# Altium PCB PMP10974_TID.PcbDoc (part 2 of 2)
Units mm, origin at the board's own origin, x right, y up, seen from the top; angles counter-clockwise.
Board outline 80 x 60 mm, 2 copper layers (Top Layer, Bottom Layer), stack 1.575 mm thick; 90 components, 52 nets, 298 pads, 61 vias.
Unrouted connection lines stored in the file: 1.
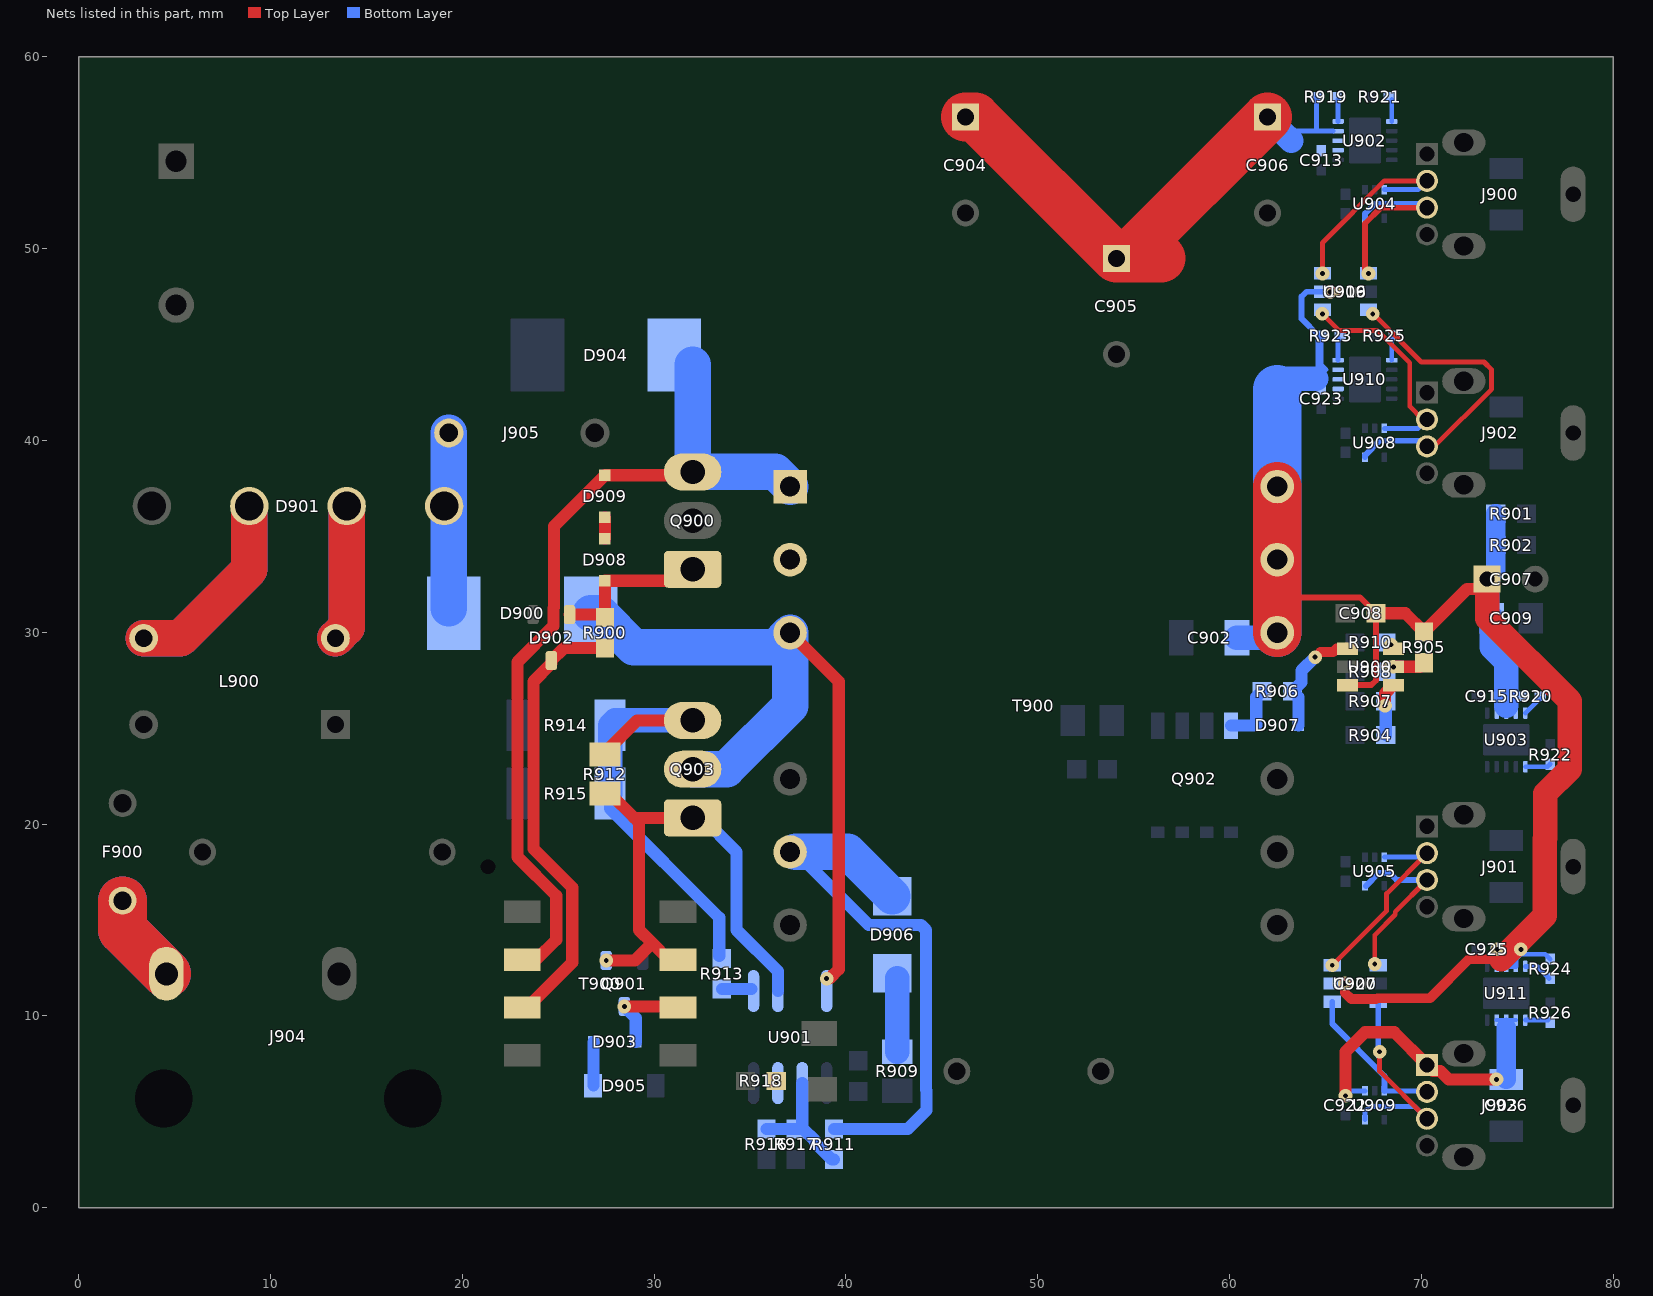
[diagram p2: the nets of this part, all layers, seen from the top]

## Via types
v1: diameter 0.711, hole 0.254, Top Layer to Bottom Layer, 44 vias
v2: diameter 0.5, hole 0.2, Top Layer to Bottom Layer, 16 vias
v3: diameter 1.524, hole 0.762, Top Layer to Bottom Layer, 1 vias

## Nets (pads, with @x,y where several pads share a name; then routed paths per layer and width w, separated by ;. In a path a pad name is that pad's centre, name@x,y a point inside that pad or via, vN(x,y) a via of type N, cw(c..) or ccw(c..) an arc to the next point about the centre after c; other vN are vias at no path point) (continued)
NetC922_1: C922.1 C926.1 J903.1 U909.1 U911.7 U911.8 U911.9 | length 17.3
  Top Layer w0.635: v1(66.04,5.834) 66.04,8.128 67.056,9.144 68.58,9.144 J903.1@70.29,7.434 70.598,7.127 70.981,7.127 71.424,6.684 v1(73.914,6.684)
  Bottom Layer w0.203: U911.9@73.922,9.776 U911.8@74.422,9.776 U911.7@74.922,9.776
  Bottom Layer w0.254: v1(66.04,5.834) 66.29,6.084 U909.1@67.064,6.084 ; 74.422,9.398 U911.8@74.422,9.776
  Bottom Layer w0.635: v1(73.914,6.684) C926.1@74.422,6.684
  Bottom Layer w1: C926.1@74.422,6.684 74.422,9.398
NetD900_1: D900.1 D901.1 J905.1 | length 9.1
  Bottom Layer w1.905: D900.1@19.29,31.243 J905.1@19.29,40.386
NetD900_2: D900.2 Q903.2 T900.3@37.084,29.972 U901.8 | length 41.1
  Top Layer w0.635: T900.3@37.084,29.972 39.624,27.432 39.624,12.43 39.134,11.94 v1(38.989,11.94)
  Bottom Layer w1.905: D900.2@26.682,30.988 27.162,30.988 28.94,29.21 36.322,29.21 T900.3@37.084,29.972 37.084,26.162 33.782,22.86 Q903.2@32.004,22.86
NetD901_2: D901.2 L900.2 | length 14.3
  Top Layer w1.905: L900.2@13.382,29.682 13.97,30.27 D901.2@13.97,36.576
  Bottom Layer w1.905: L900.2@13.382,29.682 13.97,30.27 D901.2@13.97,36.576
NetD901_3: D901.3 L900.3 | length 20.6
  Top Layer w1.905: L900.3@3.382,29.682 5.298,29.682 8.89,33.274 D901.3@8.89,36.576
  Bottom Layer w1.905: L900.3@3.382,29.682 5.298,29.682 8.89,33.274 D901.3@8.89,36.576
NetD902_1: D902.1 D908.1 Q900.1 R900.2 | length 7.6
  Top Layer w0.635: D902.1@25.588,30.918 R900.2@27.286,30.918 ; R900.2@27.432,30.772 D908.1@27.432,32.682 Q900.1@31.412,32.682
NetD902_3: D902.3 R900.1 T900.6@23.113,10.434 | length 23.6
  Top Layer w0.635: T900.6@23.113,10.434 23.388,10.434 25.727,12.773 25.727,16.691 23.706,18.712 23.706,27.432 24.638,28.364 D902.3@24.638,28.518 25.292,29.172 R900.1@27.432,29.172
NetD903_1: D903.1 D905.1 | length 2.3
  Bottom Layer w0.635: D905.1@26.84,6.38 D903.1@26.84,8.636
NetD903_2: D903.2 Q901.3 T900.3@31.243,10.434 | length 4.8
  Top Layer w0.635: v1(28.448,10.484) T900.3@31.193,10.484
  Bottom Layer w0.635: v1(28.448,10.484) 29.04,9.892 D903.2@29.04,8.636
NetD904_1: D904.1 D909.1 Q900.3 T900.1@37.084,37.592 T900.2@37.084,33.782 T900.7@23.113,12.934 | length 44.5
  Top Layer w0.635: T900.7@23.113,12.934 23.856,12.934 24.892,13.97 24.892,16.256 22.871,18.277 22.871,28.448 24.753,30.33 24.753,31.264 24.771,31.281 24.771,35.522 D909.1@27.432,38.184 Q900.3@31.834,38.184
  Bottom Layer w1.905: D904.1@32.004,43.955 Q900.3@32.004,38.354 36.322,38.354 T900.1@37.084,37.592
NetD906_1: D906.1 R909.2 | length 3.8
  Bottom Layer w1.27: R909.2@42.672,8.128 D906.1@42.672,11.97
NetD906_2: D906.2 R911.2 T900.5@37.084,18.542 | length 29.1
  Bottom Layer w0.635: T900.5@37.376,18.542 41.186,14.732 43.904,14.732 44.168,14.468 44.168,6.124 44.196,6.096 44.196,5.08 43.218,4.102 R911.2@39.37,4.102
  Bottom Layer w1.905: T900.5@37.376,18.542 40.1,18.542 D906.2@42.418,16.224
NetD907_1: D907.1 R906.2 U900.4 | length 5.2
  Top Layer w0.508: 64.731,28.973 65.407,28.973 65.578,29.144 U900.4@66.136,29.144
  Bottom Layer w0.635: R906.2@63.284,26.924 63.754,27.394 63.754,27.996 v1(64.46,28.702) ; D907.1@63.584,25.146 R906.2@63.584,26.624
NetD907_2: D907.2 Q902.4 R906.1 | length 3.2
  Bottom Layer w0.635: Q902.4@60.071,25.128 61.366,25.128 D907.2@61.384,25.146 61.384,26.624 R906.1@61.684,26.924
NetD908_2: D908.2 D909.2 | length 1.1
  Top Layer w0.635: D908.2@27.432,34.882 D909.2@27.432,35.984
NetF900_2: F900.2 J904.1 | length 9.5
  Top Layer w2.54: F900.2@2.286,16.002 2.286,14.476 J904.1@4.572,12.19
  Bottom Layer w2.54: F900.2@2.286,16.002 2.286,14.476 J904.1@4.572,12.19
NetJ900_2: J900.2 U904.3 U906.6 | length 10.8
  Top Layer w0.254: v1(64.84,48.702) 64.84,50.3 68.072,53.532 J900.2@70.29,53.532
  Bottom Layer w0.254: U904.3@68.064,53.074 69.832,53.074 J900.2@70.29,53.532
NetJ900_3: J900.3 U904.5 U906.1 | length 10
  Top Layer w0.305: v1(67.24,48.702) 67.056,48.886 67.056,51.308 67.88,52.132 J900.3@70.29,52.132
  Bottom Layer w0.305: U904.5@67.064,51.574 67.064,51.824 67.564,52.324 70.098,52.324 J900.3@70.29,52.132
NetJ901_2: J901.2 U905.3 U907.6 | length 9.9
  Top Layer w0.254: v1(65.348,12.634) 68.182,15.468 68.182,16.372 J901.2@70.29,18.48
  Bottom Layer w0.254: U905.3@68.064,18.276 J901.2@70.086,18.276
NetJ901_3: J901.3 U905.5 U907.1 | length 9.1
  Top Layer w0.254: v1(67.564,12.7) 67.564,14.208 68.636,15.28 68.636,15.426 J901.3@70.29,17.08
  Bottom Layer w0.305: U905.5@67.117,16.776 67.787,17.446 68.341,17.446 68.707,17.08 J901.3@70.29,17.08
NetJ902_2: J902.2 U906.4 U908.3 | length 11.3
  Top Layer w0.254: v1(64.835,46.598) 65.713,45.72 67.716,45.72 69.388,44.048 69.388,41.776 J902.2@70.078,41.086
  Bottom Layer w0.254: U908.3@68.064,40.628 69.832,40.628 J902.2@70.29,41.086
NetJ902_3: J902.3 U906.3 U908.5 | length 16.4
  Top Layer w0.254: v1(67.463,46.598) 67.481,46.598 69.99,44.088 73.26,44.088 73.66,43.688 73.66,43.503 73.662,43.501 73.662,42.669 J902.3@70.679,39.686
  Bottom Layer w0.305: U908.5@67.064,39.128 67.064,39.228 67.818,39.982 69.994,39.982 J902.3@70.29,39.686
NetJ903_2: J903.2 U907.4 U909.3 | length 7.9
  Bottom Layer w0.254: U909.3@68.066,6.084 J903.2@70.24,6.084
  Bottom Layer w0.305: U907.4@65.348,10.734 65.348,9.582 68.066,6.864 U909.3@68.066,6.084
NetJ903_3: J903.3 U907.3 U909.5 | length 11.4
  Top Layer w0.254: v1(67.818,8.128) 67.818,7.106 J903.3@70.29,4.634
  Bottom Layer w0.254: U909.5@67.064,4.584 67.064,5.028 67.31,5.274 69.65,5.274 J903.3@70.29,4.634
  Bottom Layer w0.305: v1@67.748,7.896 U907.3@67.748,10.734
NetQ901_1: Q901.1 Q903.1 R912.2 T900.2@31.243,12.934 U901.6 | length 27.7
  Top Layer w0.635: R912.2@27.432,21.59 27.686,21.59 28.956,20.32 ; v1(27.498,12.884) 28.993,12.884 29.899,13.789 ; T900.2@31.243,12.934 31.223,12.954 30.734,12.954 29.899,13.789 ; Q903.1@32.004,20.32 28.956,20.32 ; 28.956,20.32 29.21,20.066 29.21,14.478 29.899,13.789
  Bottom Layer w0.635: Q903.1@32.004,20.32 32.512,20.32 34.29,18.542 34.29,14.478 36.449,12.319 U901.6@36.449,11.29
NetQ903_3: Q903.3 R912.1 R913.2 R914.2 R915.2 | length 24.2
  Top Layer w0.635: R912.1@27.432,23.622 27.432,23.723 29.109,25.4 Q903.3@32.004,25.4
  Bottom Layer w0.635: R915.2@27.7,21.59 27.7,20.814 33.396,15.118 R913.2@33.396,13.123
  Bottom Layer w1.27: R915.2@27.7,21.59 R914.2@27.7,25.146 27.954,25.4 Q903.3@32.004,25.4
NetR904_1: R904.1 R907.2 U900.1 | length 2.7
  Top Layer w0.635: v1(68.098,26.162) 68.098,26.806 U900.1@68.536,27.244
  Bottom Layer w0.635: R904.1@68.136,24.638 R907.2@68.136,26.124
NetR905_1: R905.1 R908.2 U900.2 | length 1.7
  Top Layer w0.635: v1(68.536,28.194) 69.914,28.194 R905.1@70.13,28.41
NetR910_1: R910.1 U900.3
  other v1: 68.417,29.348
NetR911_1: R911.1 R916.2 R917.2 U901.2 | length 6.6
  Bottom Layer w0.635: R916.2@35.851,4.102 R917.2@37.375,4.102 37.77,4.102 38.378,3.494 38.378,3.388 39.263,2.502 R911.1@39.37,2.502 ; R917.2@37.719,4.153 U901.2@37.719,6.49
NetR913_1: R913.1 U901.5 | length 1.5
  Bottom Layer w0.635: R913.1@33.528,11.392 U901.5@35.077,11.392
NetR918_2: R918.2 U901.3
  other v1: 36.434,6.604
NetR919_1: R919.1 U902.5 | length 1.2
  Bottom Layer w0.254: U902.5@65.656,56.626 R919.1@65.656,57.78
NetR920_1: R920.1 U903.5 | length 1.1
  Bottom Layer w0.254: U903.5@75.422,25.784 R920.1@76.192,26.554
NetR921_2: R921.2 U902.6 | length 1.1
  Bottom Layer w0.254: U902.6@68.456,56.626 R921.2@68.456,57.774
NetR922_2: R922.2 U903.6 | length 1.3
  Bottom Layer w0.254: U903.6@75.422,22.984 76.57,22.984 R922.2@76.708,23.122
NetR923_1: R923.1 U910.5 | length 1.2
  Bottom Layer w0.254: U910.5@65.656,44.18 R923.1@65.656,45.344
NetR924_1: R924.1 U911.5 | length 1.5
  Bottom Layer w0.254: U911.5@75.422,12.576 76.024,12.576 R924.1@76.654,11.946
NetR925_2: R925.2 U910.6 | length 1.2
  Bottom Layer w0.254: U910.6@68.456,44.18 R925.2@68.456,45.35
NetR926_2: R926.2 U911.6 | length 1.2
  Bottom Layer w0.254: U911.6@75.422,9.776 R926.2@76.592,9.776
VOUT: C902.1 C904.1 C905.1 C906.1 C907.1 C908.1 C909.1 C913.1 C915.1 C919.1 C920.1 C923.1 C925.1 R901.2 R902.2 R905.2 R919.2 R920.2 R923.2 R924.2 T900.10 T900.11 T900.12 U900.6 U902.2 U902.3 U902.4 U903.2 U903.3 U903.4 U906.5 U907.5 U910.2 U910.3 U910.4 U911.2 U911.3 U911.4 | length 126.2
  Top Layer w0.305: 62.549,31.815 66.801,31.815 C908.1@67.628,30.988 67.628,27.486 67.386,27.244 U900.6@66.136,27.244
  Top Layer w0.508: v1(65.998,11.684) 65.998,11.218 66.342,10.874 67.645,10.874 67.693,10.922 70.46,10.922 72.492,12.954 74.168,12.954
  Top Layer w0.635: C908.1@67.628,30.988 69.152,30.988 R905.2@70.13,30.01 72.378,32.258 72.918,32.258 C907.1@73.426,32.766
  Top Layer w1.27: C907.1@73.426,32.766 73.426,30.714 77.724,26.416 77.724,22.86 76.454,21.59 76.454,19.253 76.425,19.224 76.425,15.211 74.168,12.954
  Top Layer w2.54: C904.1@46.228,56.856 46.736,56.856 C905.1@54.102,49.49 C905.1@54.61,49.49 ; 56.428,49.49 C905.1@54.61,49.49 ; C906.1@61.976,56.856 C905.1@54.61,49.49 ; T900.10@62.484,29.972 T900.11@62.484,33.782 T900.12@62.484,37.592
  Bottom Layer w0.254: 62.706,56.126 U902.4@65.396,56.126 ; 64.524,56.134 R919.2@64.524,57.912 ; R923.2@64.778,45.466 64.778,43.934 65.032,43.68 ; U911.2@73.922,12.576 U911.3@74.422,12.576 U911.4@74.922,12.576 74.922,12.946 75.184,13.208 76.446,13.208 R924.2@76.708,12.946
  Bottom Layer w0.305: 64.516,43.218 64.632,43.334 64.632,45.466 63.754,46.344 63.754,47.498 64.008,47.752 U906.5@64.84,47.752
  Bottom Layer w1: C907.1@73.426,32.766 73.876,33.216 R902.2@73.876,34.544 R901.2@73.876,36.176
  Bottom Layer w1.27: C902.1@60.378,29.718 T900.10@62.23,29.718 ; C906.1@61.976,56.856 62.706,56.126 63.206,55.626 ; 62.7,43.218 64.516,43.218 ; C907.1@73.426,32.766 73.426,30.968 C909.1@73.66,30.734 73.66,29.21 74.422,28.448 74.422,26.162
  Bottom Layer w2.54: T900.10@62.484,29.972 T900.11@62.484,33.782 T900.12@62.484,37.592 62.484,42.672
  other v1: 73.956,13.462 75.184,13.462 65.24,47.737
pads on no net: D902.2 J904.MH1 J904.MH2 T900.1@31.243,15.434 T900.4 T900.5@23.113,7.934 T900.8@23.113,15.434 U902.10 U903.10 U904.2 U905.2 U908.2 U909.2 U910.10 U911.10

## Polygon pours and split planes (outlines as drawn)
VOUT on Bottom Layer "Vout" (solid, remove dead copper, pour order 40): 65.786,55.118 65.786,56.642 65.786,57.658 65.786,58.674 64.77,59.69 63.687,59.69 44.45,59.69 44.196,59.436 44.196,58.166 44.196,57.488 53.148,48.536 53.17,48.514 54.864,48.514 54.864,49.53 60.452,55.118
GND2 on Bottom Layer "GND2" (solid, remove dead copper, pour order 42): 52.578,0.762 53.086,0.254 54.102,0.254 76.2,0.254 79.248,0.254 79.756,0.762 79.756,1.27 79.756,9.144 79.756,32.766 79.756,59.182 79.248,59.69 78.232,59.69 66.548,59.69 44.45,59.69 44.196,59.436 44.196,58.42 44.196,52.578 44.196,51.054 44.196,50.8 46.482,48.514 48.768,46.228 48.768,38.354 48.768,35.306 48.768,23.622 51.054,21.336 52.578,19.812 52.578,18.796
NetC910_2 on Bottom Layer "C910_2" (solid, remove dead copper, pour order 25): 53.34,12.192 53.594,11.938 55.118,11.938 59.69,11.938 62.992,11.938 64.77,13.716 65.278,14.224 65.278,18.288 65.278,18.542 65.786,19.05 67.056,20.32 67.056,23.876 67.056,24.638 66.802,24.892 66.461,24.892 65.786,24.892 64.262,23.368 57.912,23.368 53.594,23.368 53.34,23.114
NetD904_1 on Bottom Layer "D904_1" (solid, remove dead copper, pour order 27): 30.48,45.974 30.48,44.881 30.505,44.856 30.48,44.831 30.48,44.704 30.48,40.64 30.48,37.846 30.734,37.592 31.242,37.592 35.052,37.592 36.068,36.576 36.576,36.576 38.1,36.576 38.354,36.83 38.354,39.624 38.354,45.72 38.1,45.974
NetQ903_3 on Bottom Layer "Q903_3" (solid, remove dead copper, pour order 28): 33.274,26.416 33.499,26.191 33.499,26.162 33.499,25.908 33.499,24.892 33.499,24.863 33.274,24.638 32.766,24.638 30.48,24.638 29.718,23.876 29.718,23.368 29.718,21.336 28.702,20.32 28.522,20.14 27.178,20.14 27.104,20.14 26.67,20.574 26.416,20.828 26.416,21.336 26.416,26.162 26.67,26.416
NetD900_2 on Bottom Layer "D900_2" (solid, remove dead copper, pour order 29): 25.4,32.512 28.207,32.512 28.702,32.512 29.21,32.004 29.972,31.242 30.988,31.242 37.592,31.242 38.1,30.734 38.1,30.48 38.1,27.432 38.1,25.4 37.338,24.638 36.576,23.876 36.322,23.876 36.068,23.622 34.544,22.098 33.02,22.098 33.02,23.368 34.544,24.892 34.544,26.162 34.544,26.924 34.036,27.432 33.499,27.432 30.988,27.432 30.48,27.94 29.21,27.94 25.908,27.94 25.4,28.448
NetC914_1 on Bottom Layer "C914" (solid, remove dead copper, pour order 32): 68.326,56.134 69.596,56.134 70.104,56.134 70.866,55.372 71.628,54.61 74.168,54.61 75.068,54.61 75.322,54.356 75.322,54.102 75.322,53.478 74.93,53.086 73.406,53.086 71.882,53.086 70.612,54.356 70.578,54.39 69.63,54.39 69.302,54.39 68.86,54.832 68.574,55.118 68.326,55.118
VOUT on Bottom Layer "Vout" (solid, remove dead copper, pour order 33): 62.484,48.006 59.69,45.212 59.69,35.814 59.69,29.21 60.198,28.702 61.328,28.702 62.992,28.702 63.754,29.464 63.754,30.48 63.754,39.116 63.754,41.656 64.008,41.91 64.262,42.164 64.516,42.164 64.719,42.164 65.069,42.515 65.227,42.672 65.506,42.672 65.786,42.672 65.786,43.688 65.278,44.196 65.278,45.166 65.278,45.466 64.516,46.228 64.516,46.99 64.77,47.244 65.024,47.244 65.278,47.244 65.532,47.498 65.54,47.506 65.54,47.752 65.532,47.752 65.278,48.006
NetC921_1 on Bottom Layer "C921_1" (solid, remove dead copper, pour order 34): 68.326,43.688 69.85,43.688 70.104,43.688 71.374,42.418 74.168,42.418 75.184,42.418 75.438,42.164 75.438,41.91 75.438,41.148 75.184,40.894 74.93,40.894 70.612,40.894 69.088,42.418 68.326,42.418
NetC917_1 on Bottom Layer "C917_1" (solid, remove dead copper, pour order 37): 73.914,23.114 74.93,23.114 74.93,22.834 74.956,22.834 75.184,22.606 75.438,22.352 75.438,20.066 75.438,18.816 75.184,18.562 75.184,18.542 74.168,18.542 71.374,18.542 70.358,18.542 69.596,19.304 69.596,20.32 69.85,20.574 70.866,20.574 71.628,19.812 73.152,19.812 73.406,20.066 73.406,20.828 73.406,22.352 73.66,22.606 73.888,22.834 73.914,22.834
VOUT on Bottom Layer "Vout" (solid, remove dead copper, pour order 38): 73.914,12.446 73.914,12.7 73.66,12.954 73.66,13.162 73.66,13.416 73.706,13.462 73.66,13.508 73.66,13.97 73.914,14.224 74.168,14.478 75.184,14.478 76.454,14.478 76.514,14.478 76.962,14.03 76.962,13.716 76.962,12.954 76.454,12.446 75.184,12.446
VOUT on Bottom Layer "Vout" (solid, remove dead copper, pour order 39): 73.914,25.654 74.93,25.654 74.93,25.934 74.956,25.934 75.184,26.162 75.438,26.416 75.438,28.448 74.422,29.464 74.422,31.242 74.422,32.258 74.422,34.069 74.422,36.322 74.168,36.576 73.914,36.576 72.898,36.576 72.644,36.322 72.644,36.068 72.644,35.306 72.644,34.798 72.644,33.274 72.644,31.496 72.644,28.956 72.644,28.194 73.66,27.178 73.66,27.02 73.66,26.162 73.914,25.908 73.914,25.654
NetC922_1 on Bottom Layer "C922_1" (solid, remove dead copper, pour order 36): 69.596,7.874 69.85,8.128 70.612,8.128 70.866,8.128 71.628,7.366 73.152,7.366 73.406,7.62 73.406,9.084 73.406,9.144 73.914,9.652 73.914,9.906 74.93,9.906 74.93,9.652 75.438,9.144 75.438,8.636 75.438,7.62 75.438,6.35 74.676,6.35 73.406,6.35 70.104,6.35 69.596,6.858
GND on Bottom Layer "GND" (solid, remove dead copper, pour order 46): 46.482,0.762 45.974,0.254 45.466,0.254 38.354,0.254 26.162,0.254 25.654,0.762 25.654,2.286 25.654,17.526 22.098,21.082 22.098,21.844 21.59,22.352 21.082,22.86 21.082,41.402 19.812,42.672 19.558,42.672 9.906,42.672 5.334,38.1 5.334,36.322 5.334,35.558 4.572,34.796 1.778,34.796 1.044,34.796 0.28,35.56 0.254,35.586 0.254,36.068 0.254,39.116 0.254,44.704 0.254,59.182 0.762,59.69 2.032,59.69 24.384,59.69 38.354,45.72 42.418,41.656 42.418,34.798 42.418,29.718 42.418,19.304 42.418,19.05 46.482,14.986
GND2 on Top Layer "GND2" (solid, remove dead copper, pour order 41): 52.578,0.762 53.086,0.254 54.102,0.254 76.2,0.254 79.248,0.254 79.756,0.762 79.756,1.27 79.756,9.144 79.756,32.766 79.756,59.182 79.248,59.69 78.232,59.69 66.548,59.69 44.45,59.69 44.196,59.436 44.196,58.42 44.196,52.578 44.196,51.054 44.196,50.8 46.482,48.514 48.768,46.228 48.768,38.354 48.768,35.306 48.768,23.622 51.054,21.336 52.578,19.812 52.578,18.796
NetC910_2 on Top Layer "C910_2" (solid, remove dead copper, pour order 26): 55.626,23.368 55.118,23.368 54.864,23.114 54.864,22.606 54.864,18.796 54.864,16.256 54.864,12.192 55.118,11.938 55.88,11.938 62.992,11.938 65.278,14.224 65.278,15.537 65.278,23.114 65.024,23.368
VOUT on Top Layer "Vout" (solid, remove dead copper, pour order 30): 62.23,28.702 62.992,28.702 63.754,29.464 63.754,29.972 63.754,32.766 63.754,42.164 60.452,45.466 60.452,51.562 60.452,53.086 63.246,55.88 63.246,58.42 63.246,59.436 62.992,59.69 62.484,59.69 44.45,59.69 44.196,59.436 44.196,58.674 44.196,56.642 54.864,45.974 55.626,45.212 55.626,33.528 55.626,29.604 56.528,28.702
VOUT on Top Layer "Vout" (solid, remove dead copper, pour order 35): 63.5,36.068 66.04,36.068 68.834,36.068 71.628,36.068 74.168,33.528 74.168,33.02 74.168,31.496 78.486,27.178 78.486,26.67 78.486,21.082 77.216,19.812 77.216,17.272 77.216,14.478 75.184,12.446 73.66,12.446 73.406,12.7 73.406,12.954 73.406,13.462 73.406,13.716 74.168,14.478 75.438,15.748 75.438,20.828 75.438,22.098 75.692,22.352 76.2,22.86 76.2,24.522 76.2,25.146 71.882,29.464 71.628,29.464 69.85,29.464 68.834,30.48 67.818,30.48 67.31,30.988 67.12,31.178 67.12,31.496 67.056,31.496 66.802,31.75 63.5,31.75
GND on Top Layer "GND" (solid, remove dead copper, pour order 43): 46.482,0.762 45.974,0.254 45.466,0.254 38.354,0.254 26.162,0.254 25.654,0.762 25.654,2.286 25.654,17.526 22.098,21.082 22.098,21.844 21.59,22.352 21.082,22.86 21.082,41.402 19.812,42.672 19.558,42.672 9.906,42.672 5.334,38.1 5.334,36.322 5.334,35.558 4.572,34.796 1.778,34.796 1.044,34.796 0.28,35.56 0.254,35.586 0.254,36.068 0.254,39.116 0.254,44.704 0.254,59.182 0.762,59.69 2.032,59.69 24.384,59.69 38.354,45.72 42.418,41.656 42.418,34.798 42.418,29.718 42.418,19.304 42.418,19.05 46.482,14.986

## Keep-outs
Keep-Out Layer:
  text ".Layer_Name" at 14.656,-21.806 h1.52

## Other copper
Top Layer:
  text ".Layer_Name" at 14.656,-21.806 h1.52
Bottom Layer:
  text ".Layer_Name" at 14.656,-21.806 h1.52

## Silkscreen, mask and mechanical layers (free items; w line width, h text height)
Top Overlay:
  lines w0.178: 7.62,41.91 7.62,59.91 40.62,59.91 40.62,41.91 7.62,41.91
  lines w0.254: 25.146,33.274 25.908,33.274 26.162,33.528
  text ".PRJ_Number" at 46.482,0.762 h1.52
  text ".PCB_Rev" at 61.722,0.762 h1.52
  text ".Layer_Name" at 14.656,-21.806 h1.52
Bottom Overlay:
  lines w0.254: 32.258,0.762 36.83,0.762 37.338,1.27 ; 39.37,1.27 39.878,0.762 40.894,0.762 ; 63.5,23.876 64.516,22.86 65.786,22.86 ; 63.754,43.942 64.516,43.942 64.77,43.688 ; 67.818,51.054 69.342,49.53 69.342,49.276 ; 73.406,27.178 74.168,27.94 ; 76.962,26.67 77.724,26.67 77.978,26.416
  text ".Layer_Name" at 14.656,-21.806 h1.52
Top Paste:
  text ".Layer_Name" at 14.656,-21.806 h1.52
Bottom Paste:
  text ".Layer_Name" at 14.656,-21.806 h1.52
Top Solder:
  text ".Layer_Name" at 14.656,-21.806 h1.52
  text ".Layer_Name" at 14.656,-21.806 h1.52
Bottom Solder:
  text ".Layer_Name" at 14.656,-21.806 h1.52
Drill Guide:
  text ".Layer_Name" at 14.656,-21.806 h1.52
M1 Board Outline:
  the board outline again, w0.178
  text ".Layer_Name" at 14.656,-21.806 h1.52
M2 Board Dimensions:
  rectangle: 0,-6.985 3.175,-3.81
  rectangle: 3.175,-10.16 12.7,-6.985
  lines w0.178: 0,-6.985 25.4,-6.985 ; 3.175,-10.16 3.175,-3.81 ; 6.35,-10.16 6.35,-3.81 ; 12.7,-10.16 12.7,-3.81 ; 19.05,-10.16 19.05,-3.81 ; 0,-10.16 25.4,-10.16 25.4,-3.81 0,-3.81 0,-10.16
  text ".Layer_Name" at 14.656,-21.806 h1.52
M3 3D STEP Top:
  text ".Layer_Name" at 14.656,-21.806 h1.52
M4 3D STEP Bottom:
  text ".Layer_Name" at 14.656,-21.806 h1.52
M5 Assembly Top:
  lines w0.254: -7.417,-23.626 160.223,-23.626 ; -7.417,-18.462 160.274,-18.462 ; -7.417,-13.297 -7.417,-28.791 94.31,-28.791 160.274,-28.791 160.274,-13.297 -7.404,-13.297 -7.404,-28.791 32.614,-28.791 ; 55.194,-28.791 55.194,-13.297 ; 87.376,-18.462 87.376,-13.297 ; 108.712,-18.462 108.712,-13.297 ; 124.511,-28.956 124.511,-23.804
  text "COMPONENTS MARKED 'DNP' SHOULD NOT BE POPULATED." at 29.299,-8.09 h1.52
  text "ASSEMBLY VARIANT:" at 29.286,-11.024 h1.52
  text ".VariantName" at 55.601,-11.024 h1.52
  text "PCB VIEWED FROM TOP SIDE" at -5.804,-16.654 h1.52
  text "BOARD #:" at 57.099,-16.654 h1.52
  text ".PRJ_Number" at 70.955,-16.654 h1.52
  text "REV:" at 92.405,-16.654 h1.52
  text ".PCB_Rev" at 99.809,-16.654 h1.52
  text "SVN REV:" at 113.69,-16.654 h1.52
  text ".VersionControl_RevNumber" at 126.543,-16.654 h1.52
  text "PLOT NAME =" at -5.804,-27.034 h1.52
  text ".plot_File_Name" at 14.656,-27.034 h1.52
  text "GENERATED    :" at 57.15,-27.034 h1.52
  text ".Print_Date" at 79.235,-27.034 h1.52
  text ".Print_Time" at 97.752,-27.034 h1.52
  text "TEXAS INSTRUMENTS" at 129.87,-27.034 h1.52
M6 Assembly Bottom:
  lines w0.254: -7.429,-18.474 160.261,-18.474 ; -7.379,-23.639 160.261,-23.639 ; 28.334,-28.969 28.334,-23.817 ; 44.133,-18.474 44.133,-13.31 ; 65.468,-18.474 65.468,-13.31 ; 97.65,-28.804 97.65,-13.31 ; 120.231,-28.804 160.249,-28.804 160.249,-13.31 -7.429,-13.31 -7.429,-28.804 58.534,-28.804 160.261,-28.804 160.261,-13.31
  text "COMPONENTS MARKED 'DNP' SHOULD NOT BE POPULATED." at 154.991,-8.077 h1.52
  text ".VariantName" at 128.473,-11.024 h1.52
  text "ASSEMBLY VARIANT:" at 154.864,-11.024 h1.52
  text ".VersionControl_RevNumber" at 26.302,-16.667 h1.52
  text "SVN REV:" at 39.154,-16.667 h1.52
  text ".PCB_Rev" at 53.035,-16.667 h1.52
  text "REV:" at 60.439,-16.667 h1.52
  text ".PRJ_Number" at 81.89,-16.667 h1.52
  text "BOARD #:" at 95.745,-16.667 h1.52
  text "PCB VIEWED FROM BOTTOM SIDE" at 158.648,-16.667 h1.52
  text "TEXAS INSTRUMENTS" at 22.974,-27.047 h1.52
  text ".Print_Time" at 55.093,-27.047 h1.52
  text ".Print_Date" at 73.609,-27.047 h1.52
  text "GENERATED    :" at 95.694,-27.047 h1.52
  text ".plot_File_Name" at 138.189,-27.047 h1.52
  text "PLOT NAME =" at 158.648,-27.047 h1.52
M9 Title Sheet:
  drawing of 57 lines, arcs and shapes, not listed
  text "1" at 18.792,204.127 h1.78
  text "2" at 82.182,204.127 h1.78
  text "3" at 145.411,204.127 h1.78
  text "4" at 209.08,204.127 h1.78
  text "5" at 272.555,204.127 h1.78
  text "6" at 336.182,204.127 h1.78
  text "A" at -10.579,175.095 h1.78
  text "A" at 365.341,175.095 h1.78
  text "B" at -10.579,114.643 h1.78
  text "B" at 365.341,114.643 h1.78
  text "C" at -10.579,54.318 h1.78
  text "C" at 365.341,54.318 h1.78
  text "PROJECT TITLE:" at 288.125,7.048 h1.14
  text ".PRJ_Title" at 289.395,3.662 h1.78
  text "DESIGNED FOR:" at 288.125,-0.597 h1.14
  text ".PRJ_Customer" at 289.395,-4.153 h1.78
  text "D" at -10.579,-5.88 h1.78
  text "D" at 365.341,-5.88 h1.78
  text "FILE NAME:" at 288.125,-8.217 h1.14
  text ".PCB_File_Name_No_Path" at 289.395,-11.265 h1.78
  text "Texas Instruments (TI) and/or its licensors do not warrant the accuracy or completeness of this specification" at 161.9,-15.376 h1.14
  text "ENGINEER:" at 288.125,-15.583 h1.14
  text "LAYOUT BY:" at 326.352,-15.583 h1.14
  text "or any information contained therein. TI and/or its licensors do not warrant that this design will meet" at 160.757,-18.237 h1.14
  text ".PRJ_Engineer" at 289.395,-19.52 h1.78
  text ".PCB_Layout" at 327.635,-19.52 h1.78
  text "the specifications, will be suitable for your application or fit for any particular purpose, or will operate in" at 160.757,-21.099 h1.14
  text ".Layer_Name" at 14.656,-21.806 h1.52
  text "ALTIUM DESIGNER VERSION:" at 326.352,-23.457 h1.14
  text "an implementation. TI and/or its licensors do not warrant that the design is production worthy. You should" at 160.757,-23.961 h1.14
  text "completely validate and test your design implementation to confirm the system functionality for your application." at 161.9,-26.822 h1.14
  text ".print_Scale" at 289.395,-26.843 h1.78
  text ".Application_BuildNumber" at 327.635,-26.843 h1.78
  text "1" at 18.792,-32.093 h1.78
  text "2" at 82.182,-32.093 h1.78
  text "3" at 145.411,-32.093 h1.78
  text "4" at 209.08,-32.093 h1.78
  text "5" at 272.555,-32.093 h1.78
  text "6" at 336.182,-32.093 h1.78
M10 Fab Notes:
  drawing of 185 lines, arcs and shapes, not listed
  text "DESIGN INFORMATION" at 314.478,150.114 h1.52
  text "MIN. TRACK WIDTH:" at 298.106,145.542 h1.52
  text "10" at 325.12,145.542 h1.52
  text "MIL" at 329.881,145.542 h1.52
  text "MIN. CLEARANCE:" at 298.106,142.189 h1.52
  text "0.2" at 324.427,142.189 h1.52
  text "mm" at 329.881,142.189 h1.52
  text "MIN. VIA PAD SIZE:" at 298.106,138.836 h1.52
  text "10" at 325.189,138.836 h1.52
  text "MIL" at 329.881,138.836 h1.52
  text "0.05mm (2MIL)" at 315.759,135.237 h1.52
  text "MINIMUM ANNULAR RING" at 289.744,135.128 h1.52
  text "EXTERNAL" at 333.742,135.128 h1.52
  text "PER" at 294.824,132.131 h1.52
  text "IPC-D-275 CLASS 2 LEVEL C" at 300.412,132.131 h1.52
  text "MIL, HOLES" at 338.213,129.279 h1.52
  text "+/-" at 328.244,129.261 h1.52
  text "+/-" at 349.936,129.261 h1.52
  text "REGISTRATION TOLERANCES:" at 289.744,129.134 h1.52
  text "METAL" at 320.218,129.134 h1.52
  text "5" at 334.853,129.134 h1.52
  text "3" at 356.012,129.134 h1.52
  text "MIL" at 358.964,129.134 h1.52
  text "MATERIAL:" at 287.844,123.813 h1.52
  text "FR-4 High Tg" at 312.9,120.249 h1.52
  text "FR-408" at 298.538,120.031 h1.52
  text "X" at 309.003,120.031 h1.52
  text "OTHER" at 336.333,120.031 h1.52
  text "62 MIL (1.6mm) +/-10%" at 306.668,115.898 h1.52
  text "THICKNESS:" at 289.744,115.789 h1.52
  text "X" at 303.413,115.789 h1.52
  text "OTHER" at 339.305,115.789 h1.52
  text "TOLERANCE:" at 289.744,111.776 h1.52
  text "X" at 311.062,111.776 h1.52
  text "ANSI IPC-6012 TYPE 3 CLASS 2" at 315.81,111.776 h1.52
  text "OTHER +/-" at 315.81,107.814 h1.52
  text "BOW & TWIST:" at 289.744,103.826 h1.52
  text "X" at 311.062,103.826 h1.52
  text "ANSI IPC-6012 TYPE 3 CLASS 2" at 315.81,103.826 h1.52
  text "OTHER +/-" at 315.81,99.8 h1.52
  text "DRILLING:" at 287.844,96.282 h1.52
  text "REFERENCE:" at 289.744,93.31 h1.52
  text "X" at 306.209,93.31 h1.52
  text "AS SHOWN" at 310.958,93.31 h1.52
  text "X" at 329.094,93.31 h1.52
  text "NC_DRILL FILES" at 332.574,93.31 h1.52
  text "PTH MIN COPPER THICKNESS:" at 289.744,89.297 h1.52
  text "X" at 324.039,89.297 h1.52
  text "1MIL" at 327.519,89.297 h1.52
  text "OTHER" at 340.143,89.297 h1.52
  text "BOARD FINISH:" at 287.844,85.259 h1.52
  text "SILKSCREEN:" at 291.787,82.261 h1.52
  text "X" at 315.886,82.261 h1.52
  text "TOP" at 319.086,82.261 h1.52
  text "X" at 328.84,82.261 h1.52
  text "BOTTOM" at 332.066,82.261 h1.52
  text "SILKSCREEN COLOR:" at 291.787,78.02 h1.52
  text "X" at 315.86,78.02 h1.52
  text "WHITE" at 319.086,78.02 h1.52
  text "OTHER" at 332.066,78.02 h1.52
  text "SOLDER RESIST COLOR:" at 291.787,73.702 h1.52
  text "X" at 306.208,69.658 h1.52
  text "GREEN" at 309.434,69.658 h1.52
  text "BLUE" at 324.446,69.658 h1.52
  text "OTHER" at 338.111,69.658 h1.52
  text "IMMERSION GOLD (ENIG)" at 314.794,64.87 h1.52
  text "ENEPIG" at 348.767,64.786 h1.52
  text "SURFACE FINISH:" at 287.844,64.761 h1.52
  text "IMM. TIN/SILVER OR EQUIV" at 296.215,60.773 h1.52
  text "OTHER" at 332.574,60.773 h1.52
  text "X" at 292.1,60.706 h1.52
  text "ARRAY/PANEL:" at 287.844,56.226 h1.52
  text "CUT AND TRIM PER MECH LAYER 1" at 314.794,56.118 h1.52
  text "N.C. ROUTE" at 314.794,52.264 h1.52
  text "X" at 332.04,52.264 h1.52
  text "V. SCORE" at 336.79,52.264 h1.52
  text "CERTIFICATION:" at 287.844,48.784 h1.52
  text "MATERIALS AND WORKMANSHIP FOR ALL PCBS" at 306.259,48.784 h1.52
  text "TO MEET OR EXCEED THE REQUIREMENTS OF:" at 306.259,46.295 h1.52
  text "X" at 296.773,42.828 h1.52
  text "ANSI IPC-A-600F CLASS ->" at 300.303,42.828 h1.52
  text "X" at 341.935,42.828 h1.52
  text "2" at 344.956,42.828 h1.52
  text "1" at 336.955,42.79 h1.52
  text "3" at 353.948,42.79 h1.52
  text "X" at 296.825,38.777 h1.52
  text "UL 94V-0" at 300.303,38.777 h1.52
  text "X" at 317.45,38.777 h1.52
  text "RoHS" at 320.928,38.777 h1.52
  text "OTHER" at 337.296,38.777 h1.52
  text "PER ORDER" at 347.381,38.777 h1.52
  text "ADDITIONAL REQUIREMENTS:" at 287.844,35.195 h1.52
  text "MICROSECTION:" at 289.744,32.274 h1.52
  text "YES" at 312.749,32.274 h1.52
  text "X" at 319.786,28.448 h1.52
  text "REQUIRED" at 334.631,28.308 h1.52
  text "BARE BOARD ELEC. TEST:" at 289.744,28.236 h1.52
  text "NONE" at 322.909,28.236 h1.52
  text "PER ORDER" at 349.668,28.236 h1.52
  text "MANUFACTURER'S UL:" at 289.744,24.248 h1.52
  text "RAIL" at 319.353,24.139 h1.52
  text "METAL" at 331.845,24.139 h1.52
  text "X" at 341.376,24.13 h1.52
  text "SILK" at 344.842,24.139 h1.52
  text ".Layer_Name" at 14.656,-21.806 h1.52
M11 Gerber Information:
  lines w0.254: -7.417,-23.626 160.223,-23.626 ; -7.417,-18.462 160.274,-18.462 ; -7.417,-13.297 -7.417,-28.791 94.31,-28.791 160.274,-28.791 160.274,-13.297 -7.404,-13.297 -7.404,-28.791 32.614,-28.791 ; 55.194,-28.791 55.194,-13.297 ; 87.376,-18.462 87.376,-13.297 ; 108.712,-18.462 108.712,-13.297 ; 124.511,-28.956 124.511,-23.804
  text "ALL ARTWORK VIEWED FROM TOP SIDE" at -5.804,-16.654 h1.52
  text "BOARD #:" at 57.099,-16.654 h1.52
  text ".PRJ_Number" at 70.955,-16.654 h1.52
  text "REV:" at 92.405,-16.654 h1.52
  text ".PCB_Rev" at 99.809,-16.654 h1.52
  text "SVN REV:" at 113.69,-16.654 h1.52
  text ".VersionControl_RevNumber" at 126.543,-16.654 h1.52
  text "LAYER NAME =" at -5.804,-21.806 h1.52
  text "PLOT NAME =" at -5.804,-27.034 h1.52
  text ".plot_File_Name" at 14.656,-27.034 h1.52
  text "GENERATED    :" at 57.15,-27.034 h1.52
  text ".Print_Date" at 79.235,-27.034 h1.52
  text ".Print_Time" at 97.752,-27.034 h1.52
  text "TEXAS INSTRUMENTS" at 129.87,-27.034 h1.52
M12 Stackup:
  drawing of 191 lines, arcs and shapes, not listed
  text "Layer" at 248.681,198.882 h1.52
  text "Name" at 259.092,198.882 h1.52
  text "Material" at 282.708,198.882 h1.52
  text "Thickness" at 304.546,198.882 h1.52
  text "Constant" at 321.052,198.882 h1.52
  text "Board Layer Stack" at 335.526,198.882 h1.52
  text "1" at 248.681,195.834 h1.52
  text "Top Overlay" at 259.092,195.834 h1.52
  text "2" at 248.681,192.786 h1.52
  text "Top Solder" at 259.092,192.786 h1.52
  text "Solder Resist" at 282.708,192.786 h1.52
  text "0.40mil" at 304.546,192.786 h1.52
  text "3.5" at 321.052,192.786 h1.52
  text "3" at 248.681,189.738 h1.52
  text "Top Layer" at 259.092,189.738 h1.52
  text "Copper" at 282.708,189.738 h1.52
  text "1.40mil" at 304.546,189.738 h1.52
  text "4" at 248.681,186.69 h1.52
  text "Dielectric1" at 259.092,186.69 h1.52
  text "FR-4" at 282.708,186.69 h1.52
  text "59.20mil" at 304.546,186.69 h1.52
  text "4.8" at 321.052,186.69 h1.52
  text "5" at 248.681,183.642 h1.52
  text "Bottom Layer" at 259.092,183.642 h1.52
  text "Copper" at 282.708,183.642 h1.52
  text "1.40mil" at 304.546,183.642 h1.52
  text "6" at 248.681,180.594 h1.52
  text "Bottom Solder" at 259.092,180.594 h1.52
  text "Solder Resist" at 282.708,180.594 h1.52
  text "0.40mil" at 304.546,180.594 h1.52
  text "3.5" at 321.052,180.594 h1.52
  text "7" at 248.681,177.546 h1.52
  text "Bottom Overlay" at 259.092,177.546 h1.52
  text ".Layer_Name" at 14.656,-21.806 h1.52
M13 Component Bodies Top:
  text ".Layer_Name" at 14.656,-21.806 h1.52
M14 Component Bodies Bottom:
  text ".Layer_Name" at 14.656,-21.806 h1.52
M15 Courtyards Top:
  text ".Layer_Name" at 14.656,-21.806 h1.52
M16 Courtyards Bottom:
  text ".Layer_Name" at 14.656,-21.806 h1.52
Drill Drawing:
  drawing of 154 lines, arcs and shapes, not listed
  text "Symbol" at 141.47,84.973 h1.83
  text "Quantity" at 149.746,84.973 h1.83
  text "Finished Hole Size" at 158.817,84.973 h1.83
  text "Plated" at 175.631,84.973 h1.83
  text "Hole Type" at 182.854,84.973 h1.83
  text "2" at 149.746,81.176 h1.52
  text "118.11mil (3.000mm)" at 158.817,81.176 h1.52
  text "NPTH" at 175.631,81.176 h1.52
  text "Round" at 182.854,81.176 h1.52
  text "16" at 149.746,77.38 h1.52
  text "7.87mil (0.200mm)" at 158.817,77.38 h1.52
  text "PTH" at 175.631,77.38 h1.52
  text "Round" at 182.854,77.38 h1.52
  text "E" at 141.233,73.9 h1.27
  text "44" at 149.746,73.584 h1.52
  text "10.00mil (0.254mm)" at 158.817,73.584 h1.52
  text "PTH" at 175.631,73.584 h1.52
  text "Round" at 182.854,73.584 h1.52
  text "1" at 149.746,69.788 h1.52
  text "30.00mil (0.762mm)" at 158.817,69.788 h1.52
  text "PTH" at 175.631,69.788 h1.52
  text "Round" at 182.854,69.788 h1.52
  text "2" at 149.746,65.991 h1.52
  text "31.00mil (0.787mm)" at 158.817,65.991 h1.52
  text "PTH" at 175.631,65.991 h1.52
  text "Round" at 182.854,65.991 h1.52
  text "16" at 149.746,62.195 h1.52
  text "31.50mil (0.800mm)" at 158.817,62.195 h1.52
  text "PTH" at 175.631,62.195 h1.52
  text "Round" at 182.854,62.195 h1.52
  text "6" at 149.746,58.399 h1.52
  text "35.00mil (0.889mm)" at 158.817,58.399 h1.52
  text "PTH" at 175.631,58.399 h1.52
  text "Round" at 182.854,58.399 h1.52
  text "8" at 149.746,54.603 h1.52
  text "35.43mil (0.900mm)" at 158.817,54.603 h1.52
  text "PTH" at 175.631,54.603 h1.52
  text "Round" at 182.854,54.603 h1.52
  text "C" at 141.233,51.123 h1.27
  text "2" at 149.746,50.806 h1.52
  text "37.40mil (0.950mm)" at 158.817,50.806 h1.52
  text "PTH" at 175.631,50.806 h1.52
  text "Round" at 182.854,50.806 h1.52
  text "D" at 141.233,47.326 h1.27
  text "2" at 149.746,47.01 h1.52
  text "38.00mil (0.965mm)" at 158.817,47.01 h1.52
  text "PTH" at 175.631,47.01 h1.52
  text "Round" at 182.854,47.01 h1.52
  text "12" at 149.746,43.214 h1.52
  text "41.34mil (1.050mm)" at 158.817,43.214 h1.52
  text "PTH" at 175.631,43.214 h1.52
  text "Round" at 182.854,43.214 h1.52
  text "2" at 149.746,39.418 h1.52
  text "43.31mil (1.100mm)" at 158.817,39.418 h1.52
  text "PTH" at 175.631,39.418 h1.52
  text "Round" at 182.854,39.418 h1.52
  text "6" at 149.746,35.621 h1.52
  text "50.00mil (1.270mm)" at 158.817,35.621 h1.52
  text "PTH" at 175.631,35.621 h1.52
  text "Round" at 182.854,35.621 h1.52
  text "4" at 149.746,31.825 h1.52
  text "59.06mil (1.500mm)" at 158.817,31.825 h1.52
  text "PTH" at 175.631,31.825 h1.52
  text "Round" at 182.854,31.825 h1.52
  text "1" at 149.746,28.029 h1.52
  text "30.00mil (0.762mm)" at 158.817,28.029 h1.52
  text "PTH" at 175.631,28.029 h1.52
  text "Slot" at 182.854,28.029 h1.52
  text "4" at 149.746,24.233 h1.52
  text "31.50mil (0.800mm)" at 158.817,24.233 h1.52
  text "PTH" at 175.631,24.233 h1.52
  text "Slot" at 182.854,24.233 h1.52
  text "A" at 141.233,20.753 h1.27
  text "8" at 149.746,20.436 h1.52
  text "39.37mil (1.000mm)" at 158.817,20.436 h1.52
  text "PTH" at 175.631,20.436 h1.52
  text "Slot" at 182.854,20.436 h1.52
  text "B" at 141.233,16.956 h1.27
  text "2" at 149.746,16.64 h1.52
  text "47.24mil (1.200mm)" at 158.817,16.64 h1.52
  text "PTH" at 175.631,16.64 h1.52
  text "Slot" at 182.854,16.64 h1.52
  text "138 Total" at 149.746,12.844 h1.52
  text ".Layer_Name" at 14.656,-21.806 h1.52

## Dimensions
0,0 to 80,0 on M2 Board Dimensions
0,-10.16 to 25.4,-10.16 on M2 Board Dimensions
0,0 to 0,60 on M2 Board Dimensions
